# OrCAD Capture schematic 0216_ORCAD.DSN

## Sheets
1 01 OverView: title: STM32 EXP; rev: 1; company: KLS; note: 010-1010; note: XXXXXXXXXXXXXXXXXXXX; note: XXXXXXXXXX
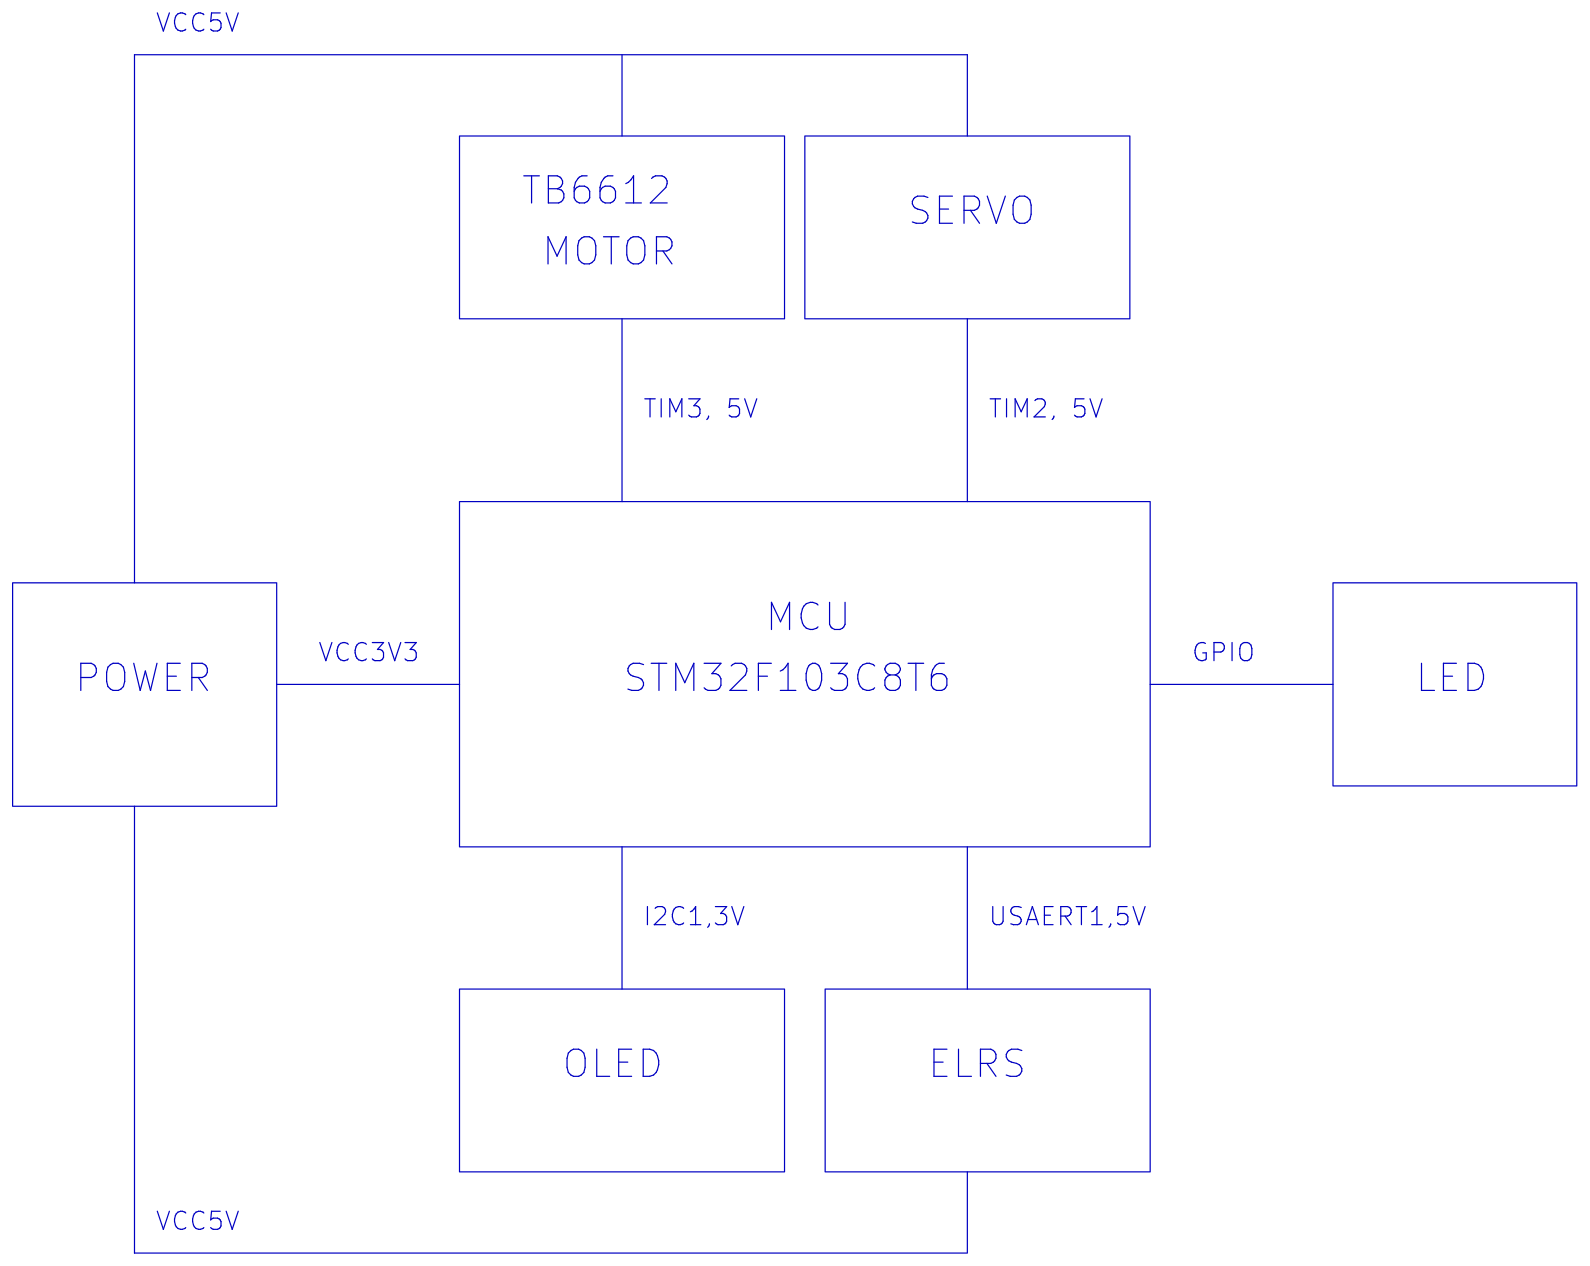
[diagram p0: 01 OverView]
2 02 Revison
3 03 MCU: size A4
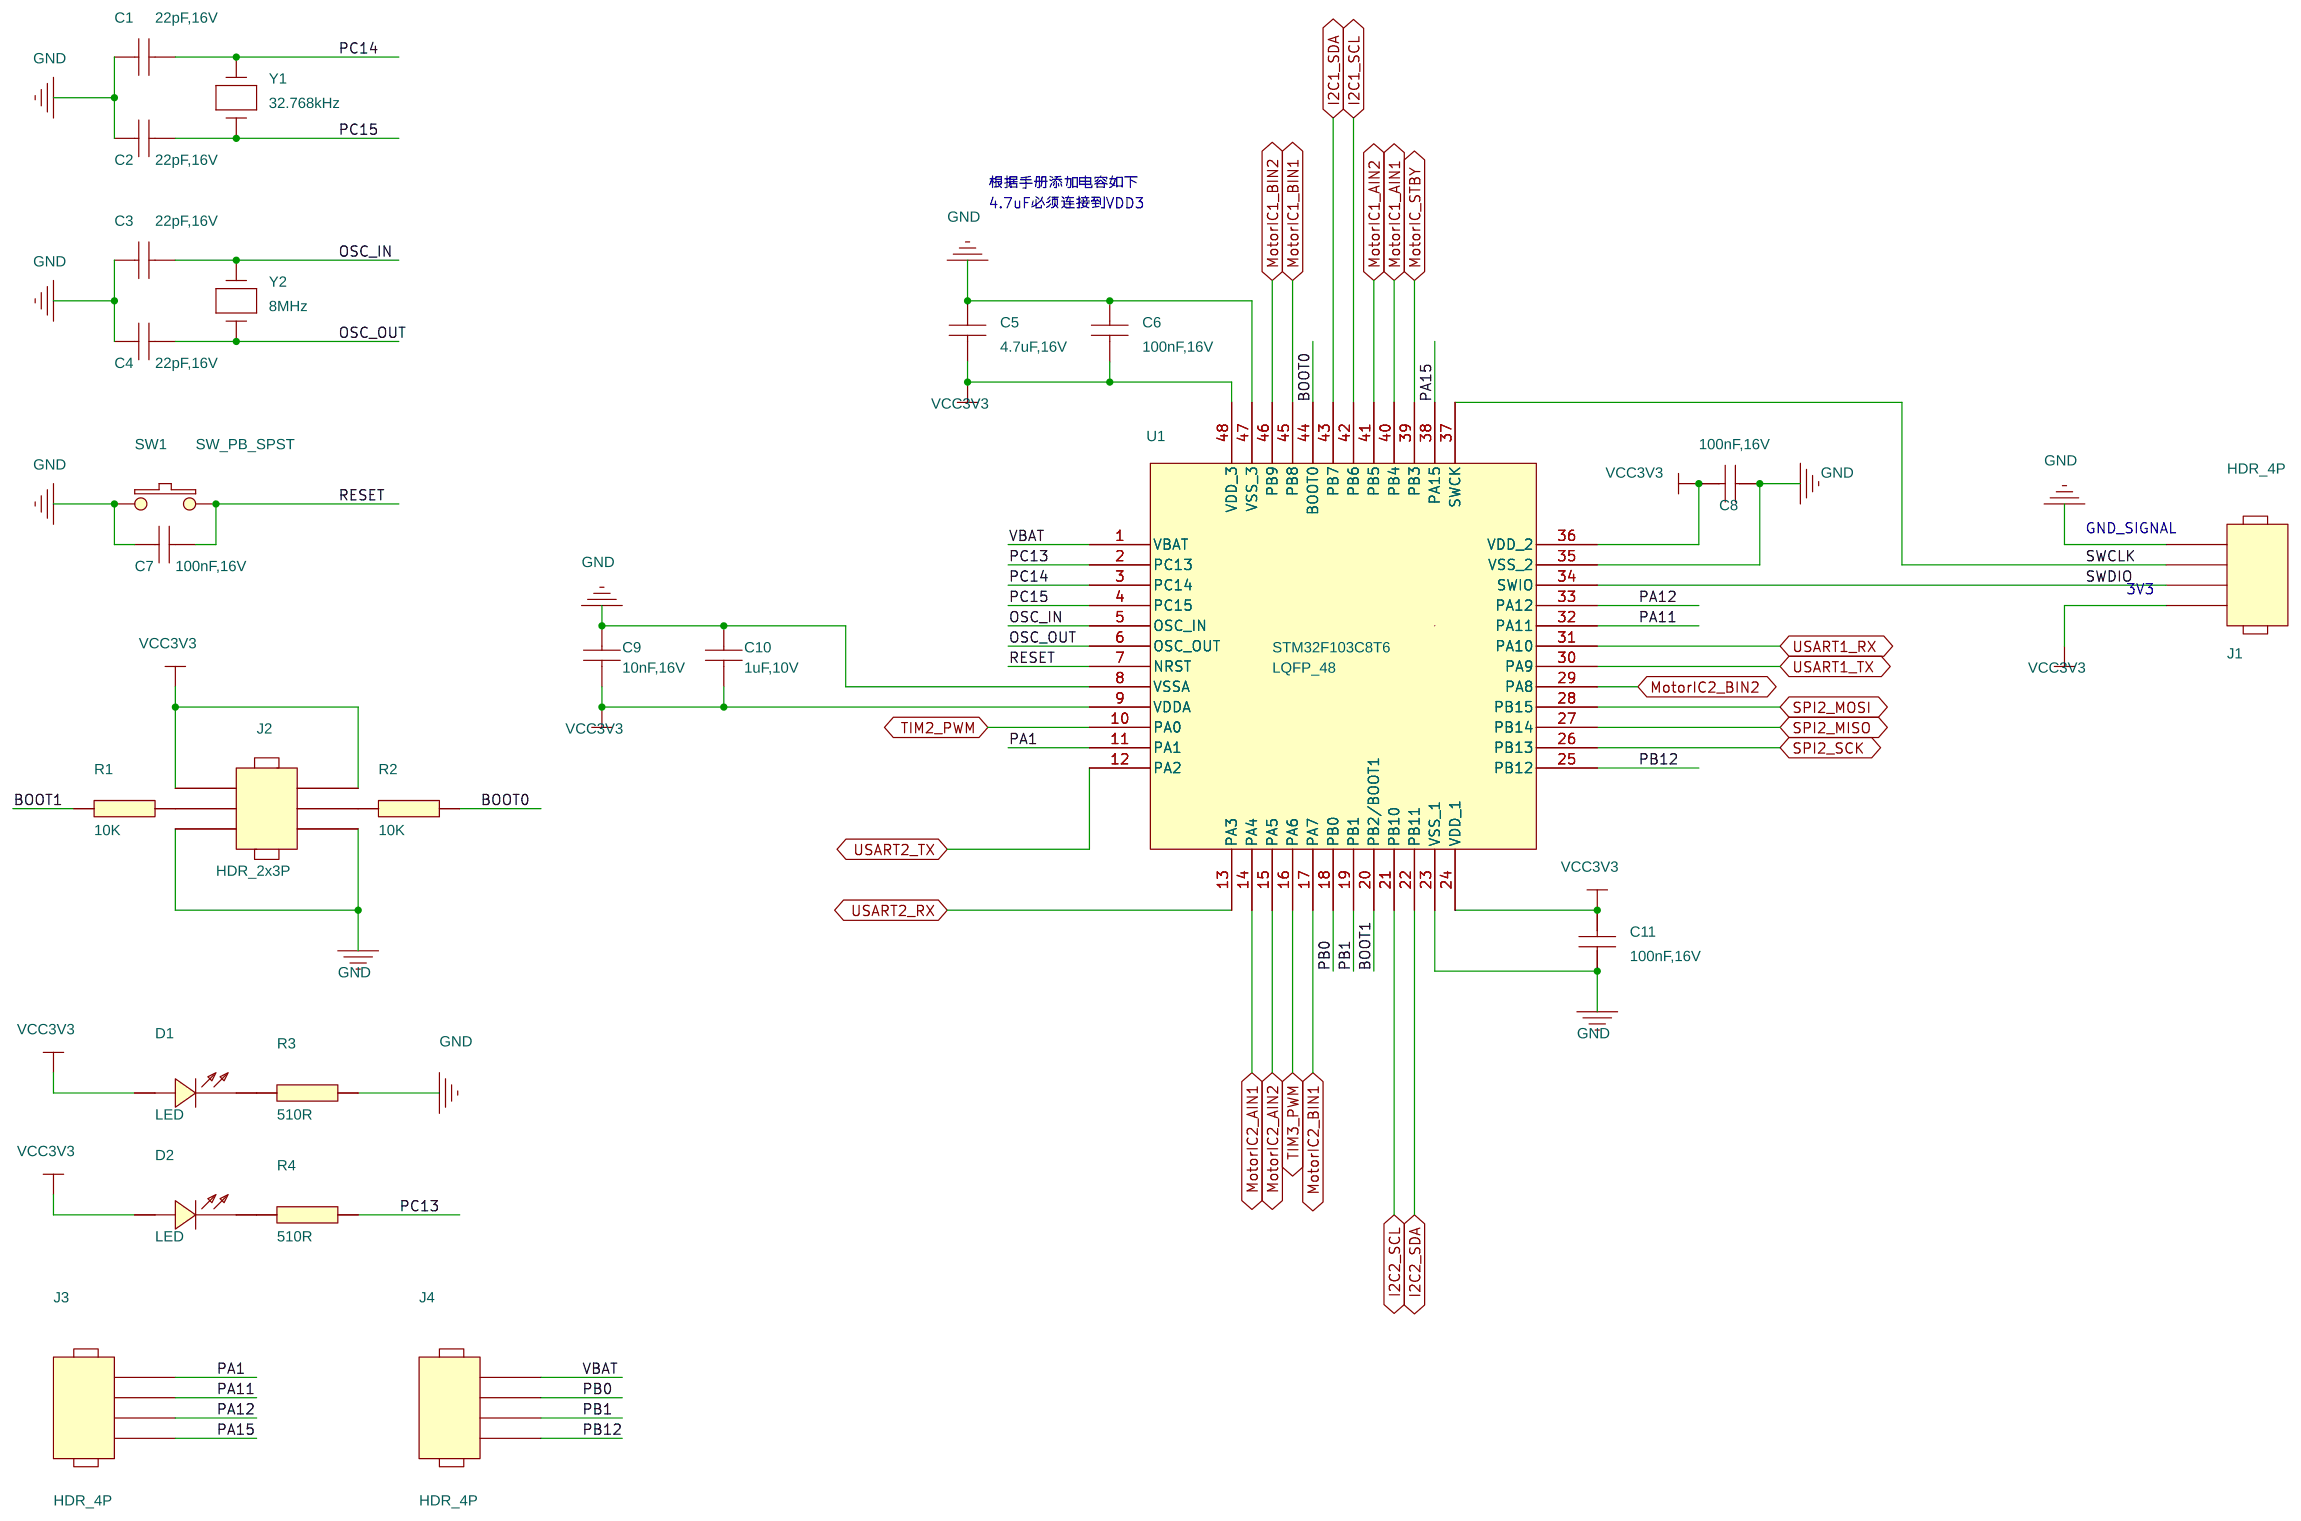
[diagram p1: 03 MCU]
4 04 POWER: size A4
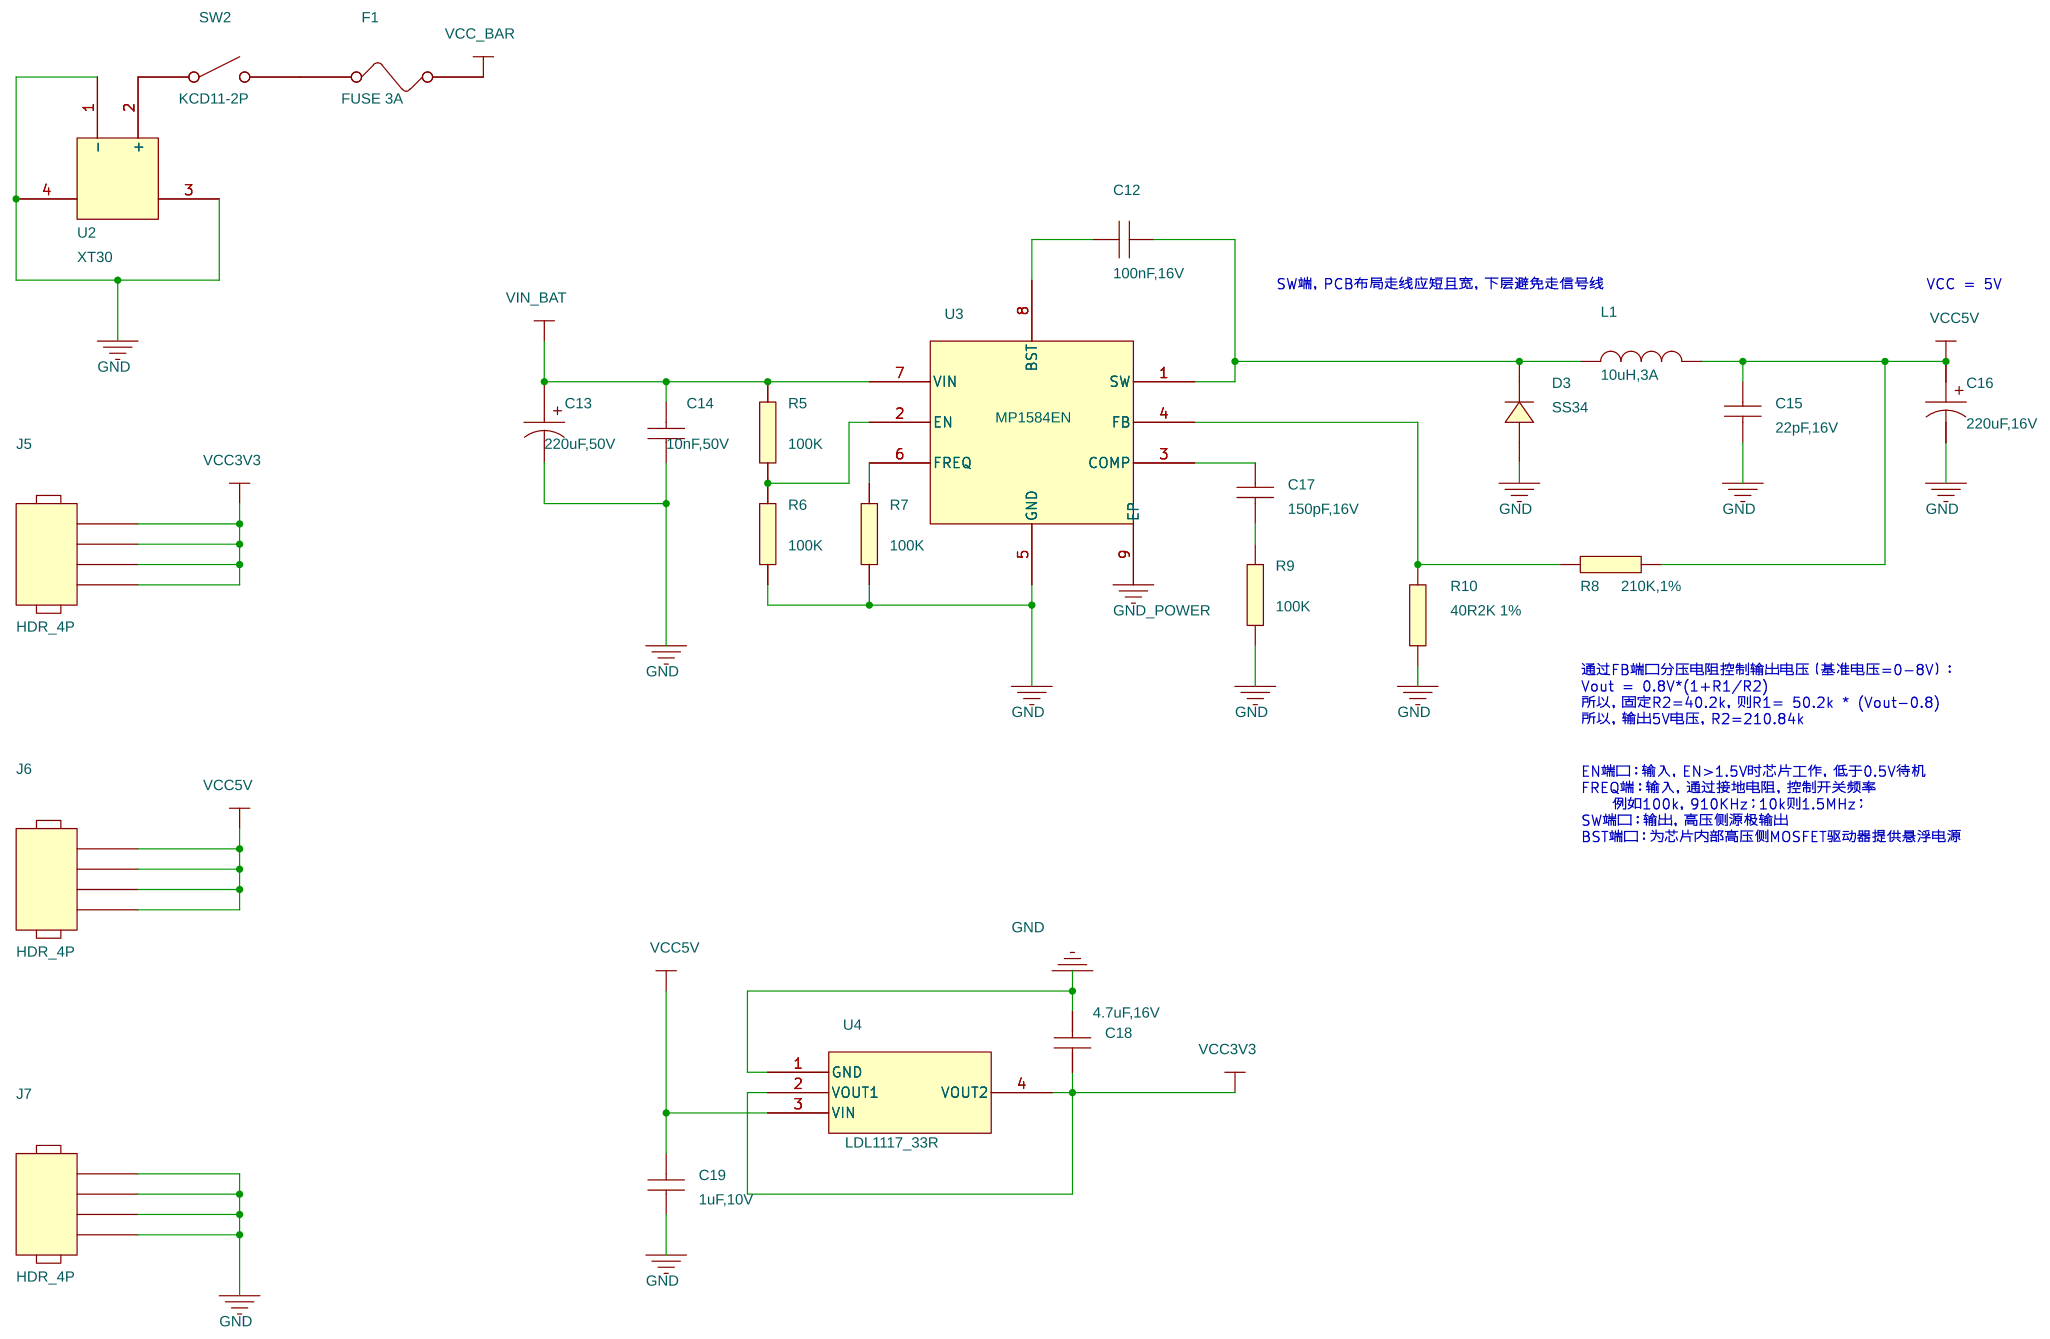
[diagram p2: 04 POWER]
5 05 MOTOR: size A4
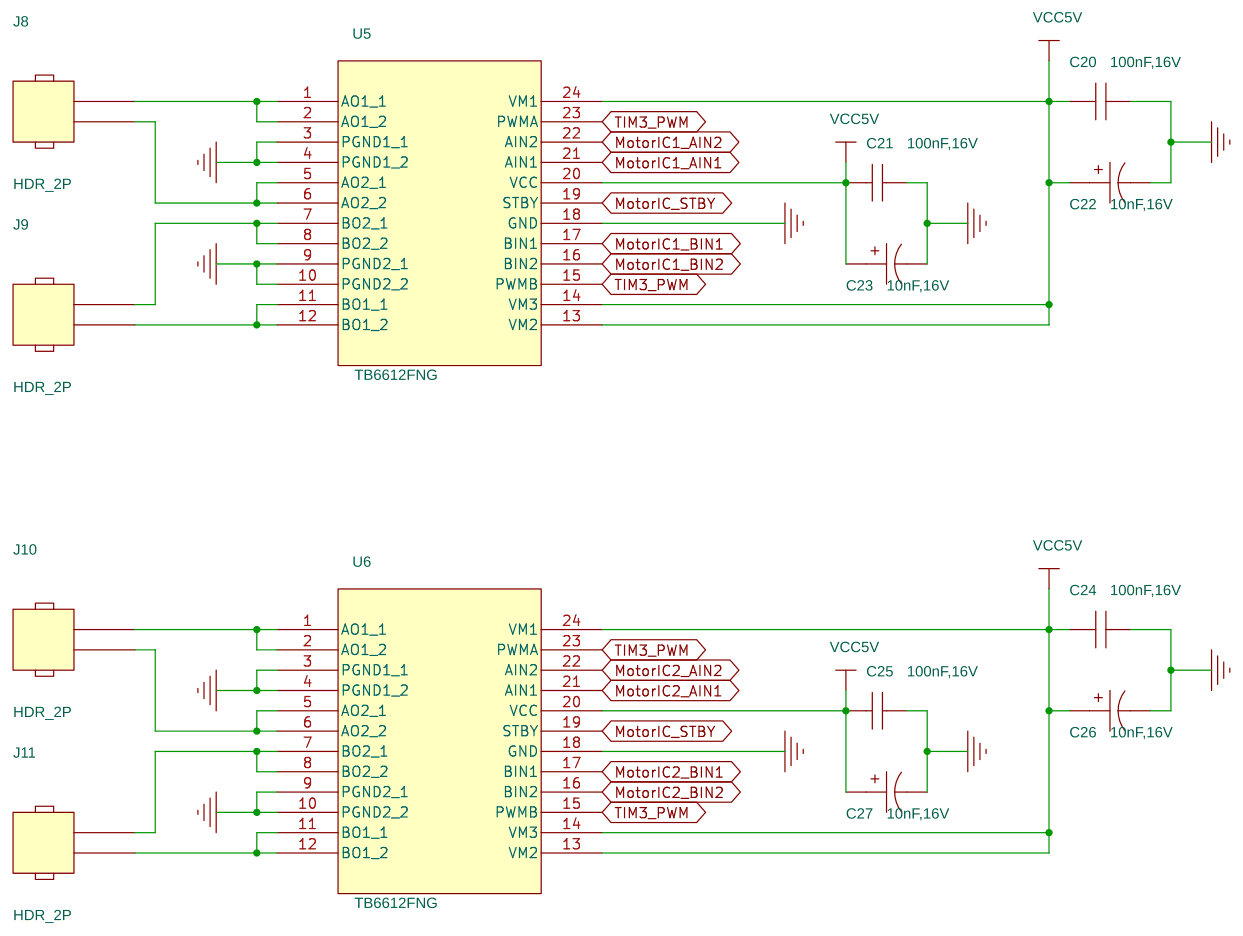
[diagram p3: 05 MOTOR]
6 06 Peripheral: size A4
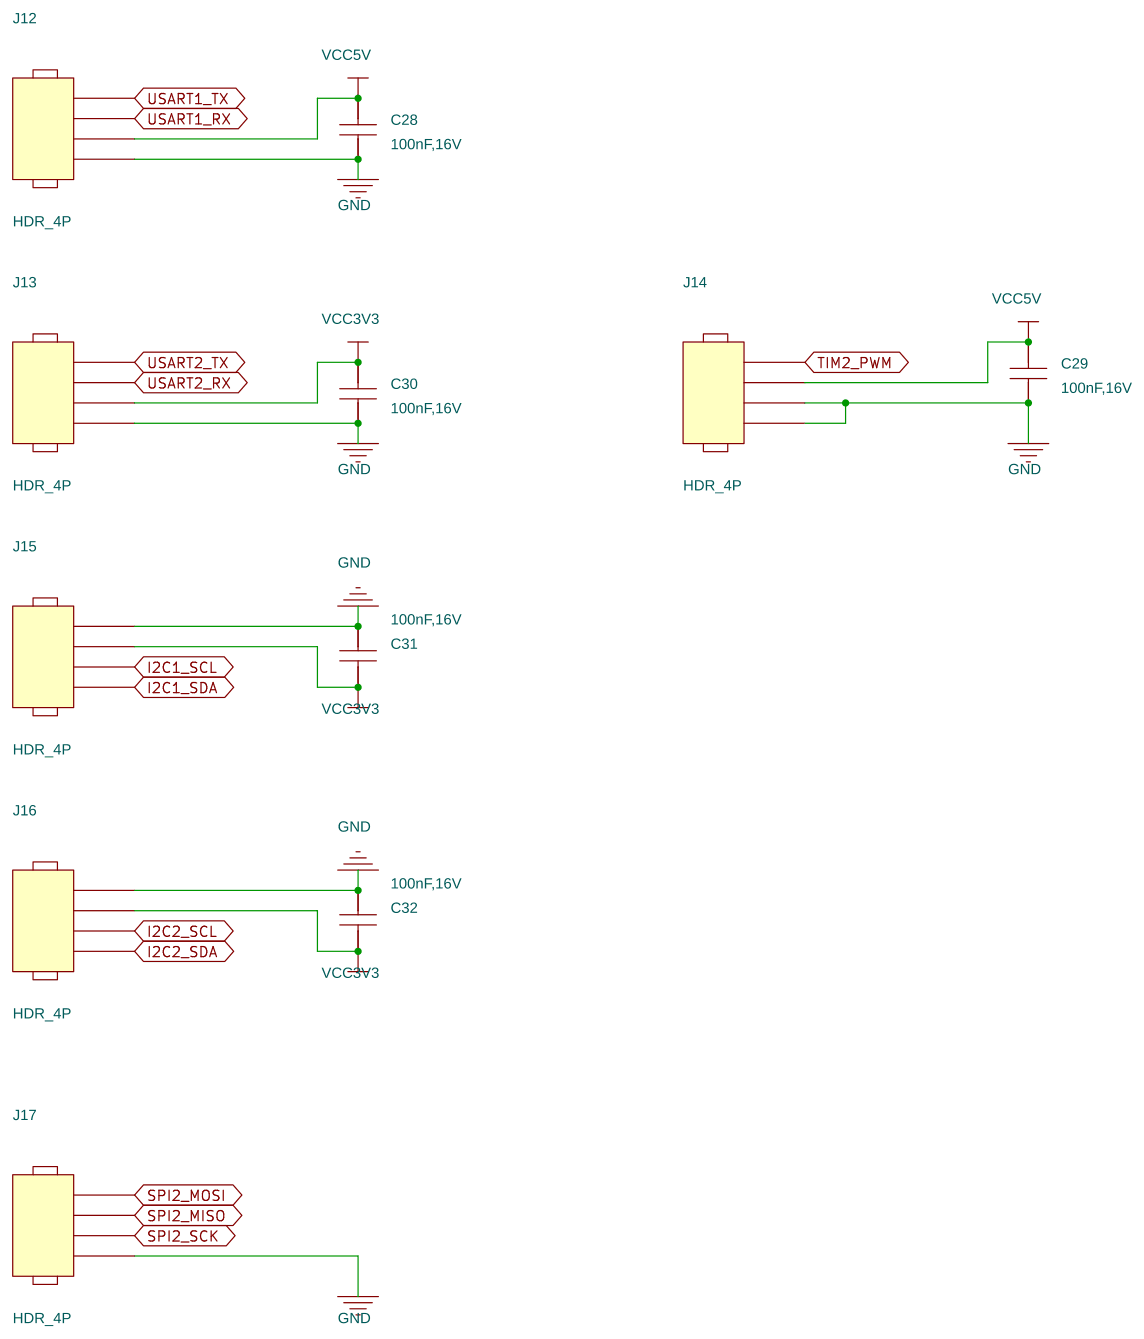
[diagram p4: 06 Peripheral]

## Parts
sheet 03 MCU
C1  22pF,16V  [C0603]
C2  22pF,16V  [C0603]
C3  22pF,16V  [C0603]
C4  22pF,16V  [C0603]
C5  4.7uF,16V  [C0603]
C6  100nF,16V  [C0603]
C7  100nF,16V  [C0603]
C8  100nF,16V  [C0603]
C9  10nF,16V  [C0603]
C10  1uF,10V  [C0603]
C11  100nF,16V  [C0603]
D1  LED  [LED0603]
D2  LED  [LED0603]
J1  HDR_4P  [HDR4_P254]
J2  HDR_2x3P  [HDR3x2_P254]
J3  HDR_4P  [HDR4_P254]
J4  HDR_4P  [HDR4_P254]
R1  10K  [R0603]
R2  10K  [R0603]
R3  510R  [R0603]
R4  510R  [R0603]
SW1  SW_PB_SPST  [SW_PB_4x3]
U1  STM32F103C8T6  [LQFP_48]
Y1  32.768kHz  [SMD_32KHz]
Y2  8MHz  [SMD_8MHz]
sheet 04 POWER
C12  100nF,16V  [C0603]
C13  220uF,50V  [CP_D10xL10R2]
C14  10nF,50V  [C0603]
C15  22pF,16V  [C0603]
C16  220uF,16V  [CP_D10xL10R2]
C17  150pF,16V  [C0603]
C18  4.7uF,16V  [C0603]
C19  1uF,10V  [C0603]
D3  SS34  [DO214AB]
F1  FUSE 3A  [SMD1812]
J5  HDR_4P  [HDR4_P254]
J6  HDR_4P  [HDR4_P254]
J7  HDR_4P  [HDR4_P254]
L1  10uH,3A  [H0630]
R5  100K  [R0603]
R6  100K  [R0603]
R7  100K  [R0603]
R8  210K,1%  [R0603]
R9  100K  [R0603]
R10  40R2K 1%  [R0603]
SW2  KCD11-2P  [KCD11-2P]
U2  XT30  [XT30]
U3  MP1584EN  [SOIC-8-EP]
U4  LDL1117_33R  [SOT223]
sheet 05 MOTOR
C20  100nF,16V  [C0603]
C21  100nF,16V  [C0603]
C22  10nF,16V  [CP_D4xL54]
C23  10nF,16V  [CP_D4xL54]
C24  100nF,16V  [C0603]
C25  100nF,16V  [C0603]
C26  10nF,16V  [CP_D4xL54]
C27  10nF,16V  [CP_D4xL54]
J8  HDR_2P  [HDR2_P254]
J9  HDR_2P  [HDR2_P254]
J10  HDR_2P  [HDR2_P254]
J11  HDR_2P  [HDR2_P254]
U5  TB6612FNG  [SSOP24]
U6  TB6612FNG  [SSOP24]
sheet 06 Peripheral
C28  100nF,16V  [C0603]
C29  100nF,16V  [C0603]
C30  100nF,16V  [C0603]
C31  100nF,16V  [C0603]
C32  100nF,16V  [C0603]
J12  HDR_4P  [HDR4_P254]
J13  HDR_4P  [HDR4_P254]
J14  HDR_4P  [HDR4_P254]
J15  HDR_4P  [HDR4_P254]
J16  HDR_4P  [HDR4_P254]
J17  HDR_4P  [HDR4_P254]

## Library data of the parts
C1-C12 C14 C15 C17-C21 C24 C25 C28-C32 = CAP_NP
D1 D2 = LED
J1 J3-J7 J12-J17 = HEADER_4
J2 = HEADER_3X2
R1-R10 = R2
SW1 = SW_PB_SPST
U1 = STM32F103C8T6
Y1 Y2 = CRYSTAL
C13 C16 C22 C23 C26 C27 = CAP_POL
D3 = DIODE
F1 = FUSE
L1 = INDUCTOR
SW2 = SW_SPST
U2 = XT30
U3 = MP1584EN
U4 = LDL1117_33R
J8-J11 = HEADER_2
U5 U6 = TB6612FNG

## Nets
GND: C1.1 C2.1 C3.1 C4.1 C5.1 C6.1 C7.1 C8.1 C9.1 C10.1 C11.1 C13.2 C14.1 C15.2 C16.2 C18.2 C19.1 C20.1 C21.1 C22.2 C23.2 C24.1 C25.1 C26.2 C27.2 C28.1 C29.1 C30.1 C31.1 C32.1 D3.2(A) J1.1 J2.5 J2.6 J7.1 J7.2 J7.3 J7.4 J12.4 J13.4 J14.3 J14.4 J15.1 J16.1 J17.4 R3.2 R6.1 R7.1 R9.1 R10.2 SW1.1 U1.8(VSSA) U1.23(VSS_1) U1.35(VSS_2) U1.47(VSS_3) U2.1(-) U2.3 U2.4 U3.5(GND) U3.9(EP) U4.1(GND) U5.3(PGND1_1) U5.4(PGND1_2) U5.9(PGND2_1) U5.10(PGND2_2) U5.18(GND) U6.3(PGND1_1) U6.4(PGND1_2) U6.9(PGND2_1) U6.10(PGND2_2) U6.18(GND)
VBAT: J4.1 U1.1(VBAT)
VCC3V3: C5.2 C6.2 C8.2 C9.2 C10.2 C11.2 C18.1 C30.2 C31.2 C32.2 D1.2(ANODE) D2.2(ANODE) J1.4 J2.1 J2.2 J5.1 J5.2 J5.3 J5.4 J13.3 J15.2 J16.2 U1.9(VDDA) U1.24(VDD_1) U1.36(VDD_2) U1.48(VDD_3) U4.2(VOUT1) U4.4(VOUT2)
VCC5V: C15.1 C16.1 C19.2 C20.2 C21.2 C22.1 C23.1 C24.2 C25.2 C26.1 C27.1 C28.2 C29.2 J6.1 J6.2 J6.3 J6.4 J12.3 J14.2 L1.2 R8.1 U4.3(VIN) U5.13(VM2) U5.14(VM3) U5.20(VCC) U5.24(VM1) U6.13(VM2) U6.14(VM3) U6.20(VCC) U6.24(VM1)
VIN_BAT: C13.1 C14.2 F1.2 R5.2 U3.7(VIN)
BOOT0: R2.2 U1.44(BOOT0)
BOOT1: R1.1 U1.20(PB2/BOOT1)
I2C1_SCL: J15.3 U1.42(PB6)
I2C1_SDA: J15.4 U1.43(PB7)
I2C2_SCL: J16.3 U1.21(PB10)
I2C2_SDA: J16.4 U1.22(PB11)
MotorIC1_AIN1: U1.40(PB4) U5.21(AIN1)
MotorIC1_AIN2: U1.41(PB5) U5.22(AIN2)
MotorIC1_BIN1: U1.45(PB8) U5.17(BIN1)
MotorIC1_BIN2: U1.46(PB9) U5.16(BIN2)
MotorIC2_AIN1: U1.14(PA4) U6.21(AIN1)
MotorIC2_AIN2: U1.15(PA5) U6.22(AIN2)
MotorIC2_BIN1: U1.17(PA7) U6.17(BIN1)
MotorIC2_BIN2: U1.29(PA8) U6.16(BIN2)
MotorIC_STBY: U1.39(PB3) U5.19(STBY) U6.19(STBY)
OSC_IN: C3.2 U1.5(OSC_IN) Y2.2
OSC_OUT: C4.2 U1.6(OSC_OUT) Y2.1
PA1: J3.1 U1.11(PA1)
PA11: J3.2 U1.32(PA11)
PA12: J3.3 U1.33(PA12)
PA15: J3.4 U1.38(PA15)
PB0: J4.2 U1.18(PB0)
PB1: J4.3 U1.19(PB1)
PB12: J4.4 U1.25(PB12)
PC13: R4.2 U1.2(PC13)
PC14: C1.2 U1.3(PC14) Y1.2
PC15: C2.2 U1.4(PC15) Y1.1
RESET: C7.2 SW1.2 U1.7(NRST)
SPI2_MISO: J17.2 U1.27(PB14)
SPI2_MOSI: J17.1 U1.28(PB15)
SPI2_SCK: J17.3 U1.26(PB13)
SWCLK: J1.2 U1.37(SWCK)
SWDIO: J1.3 U1.34(SWIO)
TIM2_PWM: J14.1 U1.10(PA0)
TIM3_PWM: U1.16(PA6) U5.15(PWMB) U5.23(PWMA) U6.15(PWMB) U6.23(PWMA)
USART1_RX: J12.2 U1.31(PA10)
USART1_TX: J12.1 U1.30(PA9)
USART2_RX: J13.2 U1.13(PA3)
USART2_TX: J13.1 U1.12(PA2)
N13546: J8.1 U5.1(AO1) U5.2(AO1)
N13563: J8.2 U5.5(AO2_1) U5.6(AO2_2)
N13598: J9.1 U5.7(BO2_1) U5.8(BO2_2)
N13619: J9.2 U5.11(BO1_1) U5.12(BO1_2)
N15223: J10.1 U6.1(AO1) U6.2(AO1)
N15263: J10.2 U6.5(AO2_1) U6.6(AO2_2)
N15407: J11.1 U6.7(BO2_1) U6.8(BO2_2)
N15519: J11.2 U6.11(BO1_1) U6.12(BO1_2)
N31972: C12.2 U3.8(BST)
N31979: C12.1 D3.1(K) L1.1 U3.1(SW)
N32592: R7.2 U3.6(FREQ)
N32821: R5.1 R6.2 U3.2(EN)
N35796: C17.1 U3.3(COMP)
N36210: C17.2 R9.2
N38494: R8.2 R10.1 U3.4(FB)
N48370: SW2.1 U2.2(+)
N48371: F1.1 SW2.2
N48721: D1.1(CATHODE) R3.1
N48722: D2.1(CATHODE) R4.1
N49463: J2.3 R2.1
N49464: J2.4 R1.2

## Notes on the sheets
sheet 1
- VCC5V
- TB6612
- SERVO
- MOTOR
- TIM3, 5V
- TIM2, 5V
- MCU
- VCC3V3
- GPIO
- POWER
- STM32F103C8T6
- LED
- I2C1,3V
- USAERT1,5V
- OLED
- ELRS
- VCC5V
sheet 3
- 4.7uF必须连接到VDD3
- 根据手册添加电容如下
- GND_SIGNAL
- 3V3
sheet 4
- SW端，PCB布局走线应短且宽，下层避免走信号线
- VCC = 5V
- 通过FB端口分压电阻控制输出电压（基准电压=0-8V）：
  Vout = 0.8V*(1+R1/R2)
  所以，固定R2=40.2k，则R1= 50.2k * (Vout-0.8)
  所以，输出5V电压，R2=210.84k
- EN端口：输入，EN>1.5V时芯片工作，低于0.5V待机
  FREQ端：输入，通过接地电阻，控制开关频率
      例如100k，910KHz；10k则1.5MHz；
  SW端口：输出，高压侧源极输出
  BST端口：为芯片内部高压侧MOSFET驱动器提供悬浮电源
